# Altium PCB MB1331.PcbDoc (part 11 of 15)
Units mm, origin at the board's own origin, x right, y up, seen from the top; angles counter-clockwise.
Board outline 169.25 x 173.25 mm, 6 copper layers (Top Layer, Signal Layer 1, Signal Layer 2, Signal Layer 3, Signal Layer 4, Bottom Layer), stack 1.556 mm thick; 871 components, 699 nets, 3244 pads, 2370 vias.
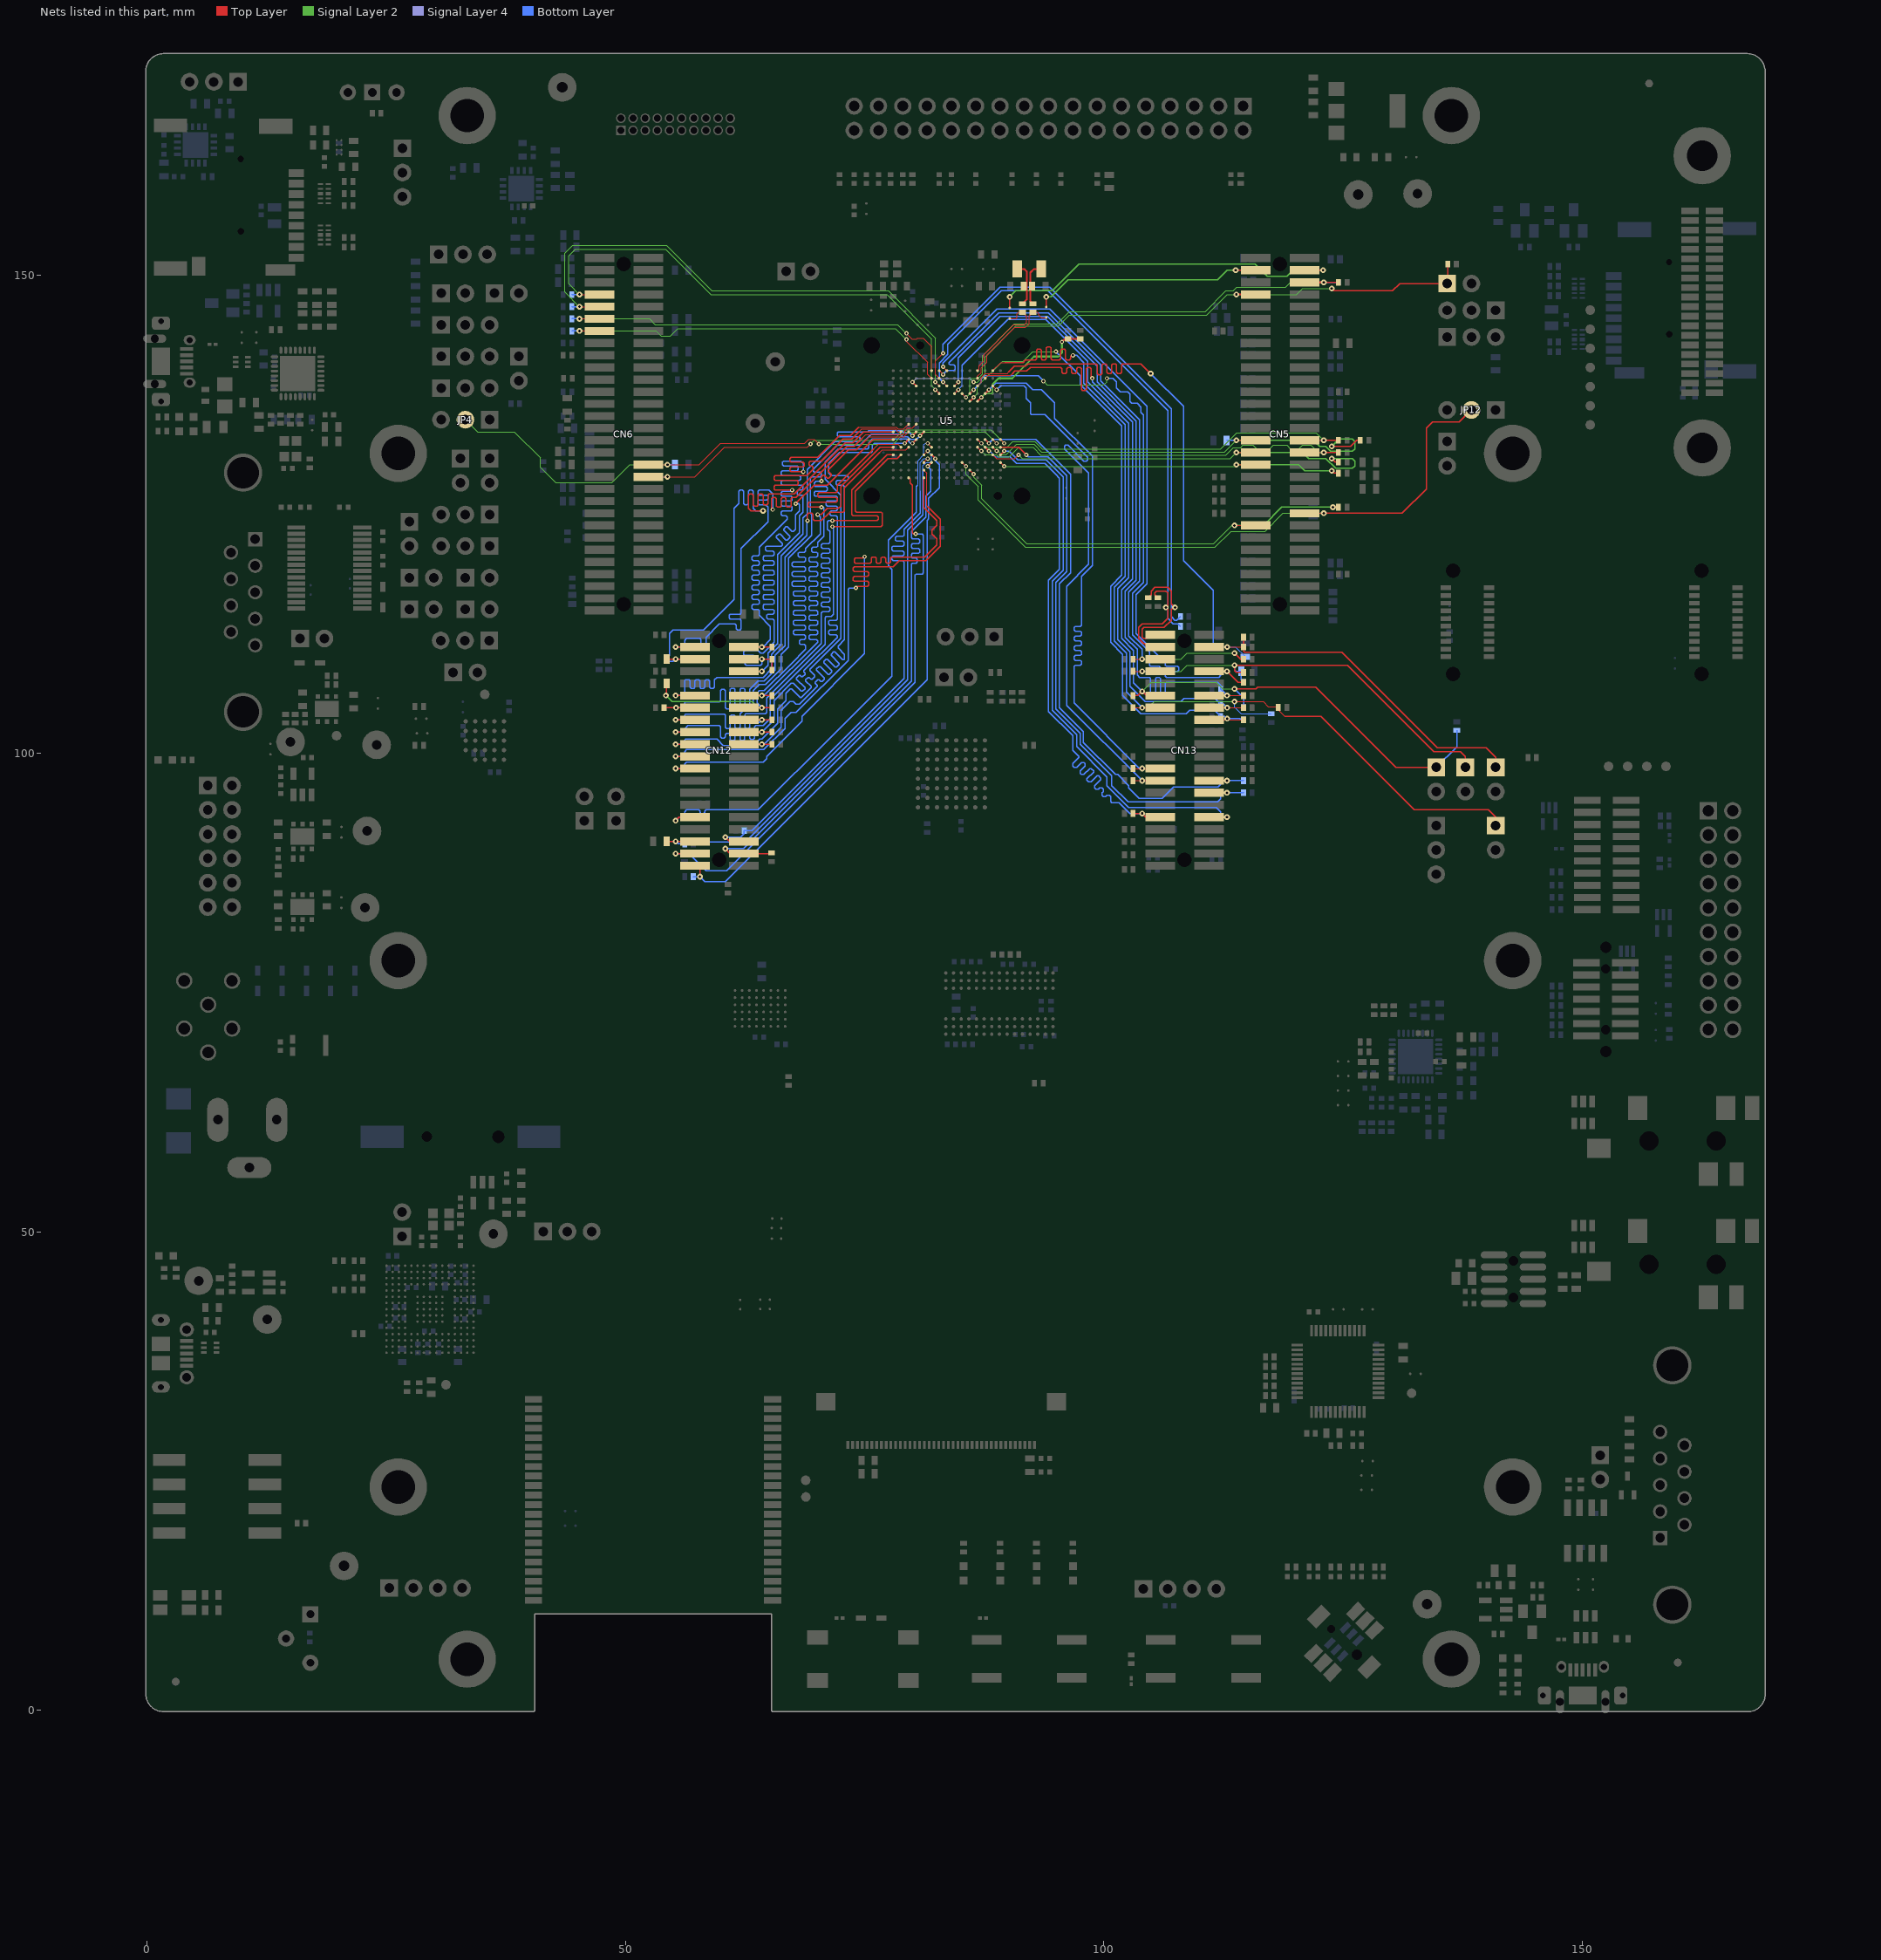
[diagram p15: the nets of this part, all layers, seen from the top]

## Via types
v1: diameter 0.6, hole 0.254, Top Layer to Bottom Layer, tented both sides, 1747 vias
v2: diameter 0.45, hole 0.2, Top Layer to Bottom Layer, tented both sides, 272 vias
v3: diameter 0.406, hole 0.203, Top Layer to Bottom Layer, tented both sides, 160 vias
v4: diameter 0.6, hole 0.25, Top Layer to Bottom Layer, tented both sides, 82 vias
v5: diameter 0.45, hole 0.25, Top Layer to Bottom Layer, tented both sides, 45 vias
v6: diameter 0.5, hole 0.25, Top Layer to Bottom Layer, tented both sides, 23 vias
v7: diameter 1.016, hole 0.508, Top Layer to Bottom Layer, tented both sides, 17 vias
v8: diameter 0.508, hole 0.254, Top Layer to Bottom Layer, tented both sides, 9 vias
v9: diameter 0.61, hole 0.305, Top Layer to Bottom Layer, tented both sides, 7 vias
v10: diameter 0.5, hole 0.254, Top Layer to Bottom Layer, tented both sides, 6 vias
v11: diameter 0.4, hole 0.2, Top Layer to Bottom Layer, tented both sides, 1 vias
v12: diameter 0.483, hole 0.254, Top Layer to Bottom Layer, tented both sides, 1 vias

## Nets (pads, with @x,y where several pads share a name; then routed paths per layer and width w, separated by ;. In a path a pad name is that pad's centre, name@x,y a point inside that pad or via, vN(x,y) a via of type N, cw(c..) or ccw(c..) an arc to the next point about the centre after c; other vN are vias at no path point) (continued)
PC8: CN5.44 JP12.2 U5.F13 | length 69.9
  Top Layer w0.1: U5.F13@85.2,130.4 v2(85.6,130) ; CN5.44@120.972,125.095 v1(122.994,125.095)
  Top Layer w0.127: v1(122.994,125.095) 131.191,125.095 133.731,127.635 133.731,133.985 134.366,134.62 137.16,134.62 JP12.2@138.43,135.89
  Signal Layer 2 w0.1: v2(85.6,130) 85.6,129.157 86.868,127.889 86.868,126.492 91.821,121.539 111.633,121.539 113.294,123.2 116.85,123.2 118.745,125.095 v1(122.994,125.095)
PC9: CN5.45 R62.2 U5.E14 | length 46.5
  Top Layer w0.1: U5.E14@86,129.6 v2(86.4,129.2) ; v1(113.665,123.825) CN5.45@115.872,123.825
  Top Layer w0.127: v1(123.952,125.73) R62.2@124.518,125.73
  Signal Layer 2 w0.1: v2(86.4,129.2) 86.4,128.865 87.249,128.016 87.249,126.619 91.948,121.92 111.506,121.92 113.411,123.825 v1(113.665,123.825)
  Signal Layer 2 w0.127: v1(113.665,123.825) 116.713,123.825 118.618,125.73 v1(123.952,125.73)
PC10: CN5.35 R56.2 U5.A13 | length 37.9
  Top Layer w0.1: U5.A13@89.2,130.4 v2(89.6,130) ; v1(113.85,130.175) CN5.35@115.872,130.175
  Top Layer w0.127: v1(123.825,129.54) 124.079,129.286 R56.2@124.518,129.286
  Signal Layer 2 w0.1: v2(89.6,130) 113.675,130 v1(113.85,130.175)
  Signal Layer 2 w0.127: v1(113.85,130.175) 120.396,130.175 121.031,129.54 v1(123.825,129.54)
PC11: CN5.34 R51.2 U5.D11 | length 42.4
  Top Layer w0.1: U5.D11@86.8,132 v2(87.2,131.6) ; CN5.34@120.972,131.445 v1(122.994,131.445)
  Top Layer w0.127: v1(122.994,131.445) R51.2@124.518,131.445
  Signal Layer 2 w0.1: v2(87.2,131.6) 87.6,131.2 88.8,131.2 89,131 90.1,131 91.1,132 92.6,132 93.409,131.191 112.776,131.191 113.538,131.953 114.3,131.953 114.554,132.207 115.57,132.207 116.078,131.699 117.221,131.699 117.729,132.207 119.126,132.207 119.507,131.826 120.396,131.826 120.777,132.207 121.666,132.207 122.428,131.445 v1(122.994,131.445)
PC12: CN5.33 R54.2 U5.B12 | length 45.3
  Top Layer w0.1: U5.B12@88.4,131.2 88.8,130.8 90.7,130.8 v2(91.1,131.2) ; v1(113.85,131.445) CN5.33@115.872,131.445
  Top Layer w0.127: v1(123.825,130.81) 124.206,130.429 R54.2@124.518,130.429
  Signal Layer 2 w0.1: v2(91.1,131.2) 91.49,130.81 113.215,130.81 v1(113.85,131.445)
  Signal Layer 2 w0.127: v1(113.85,131.445) 120.777,131.445 121.412,130.81 123.21,130.81 124.226,129.794 125.984,129.794 126.238,130.048 126.238,130.556 125.984,130.81 v1(123.825,130.81)
PC13: C97.1 CN5.6 R16.2 U5.F4 | length 49.9
  Top Layer w0.1: U5.F4@85.2,137.6 v2(85.6,137.2)
  Top Layer w0.127: v1(122.994,149.225) R16.2@124.518,149.225
  Top Layer w0.2: CN5.6@120.972,149.225 v1(122.994,149.225)
  Signal Layer 2 w0.1: v2(85.6,137.2) 86,137.6 86,139 86.2,139.2 86.876,139.2 87.33,139.654 87.33,141.559 90.678,144.907 95.123,144.907 96.393,146.177 110.617,146.177 112.776,148.336 113.555,148.336 113.919,148.7 119,148.7 119.525,149.225 v1(122.994,149.225)
  Bottom Layer w0.127: v1(122.994,149.225) C97.1@124.518,149.225
PC14: R23.2 SB8.2 U5.D1 | length 10.9
  Top Layer w0.1: U5.D1@86.8,140 86.973,140.173 86.973,140.507 87.477,141.011 87.477,141.677 90.58,144.78 91.694,144.78 91.948,145.034 91.948,145.652 R23.2@91.5,146.1 91.109,146.1 90.932,145.923 90.932,145.542 90.84,145.45 SB8.2@90.17,145.45
PC14-OSC32_IN: C25.2 R23.1 X2.2 | length 4.7
  Top Layer w0.2: X2.2@90.952,150.622 91.694,150.622 91.948,150.368 91.948,147.448 R23.1@91.5,147
PC14_E: CN5.4 SB8.1 | length 38.1
  Top Layer w0.127: SB8.1@90.17,146.55 v1(90.17,147.701) ; CN5.4@120.972,150.495 v1(122.936,150.495)
  Signal Layer 2 w0.127: v1(90.17,147.701) 90.805,148.336 94.615,148.336 97.409,151.13 115.824,151.13 117.094,149.86 119.126,149.86 119.761,150.495 v1(122.936,150.495)
PC15: R24.2 SB9.1 U5.D2 | length 11.6
  Top Layer w0.1: U5.D2@86.8,139.2 86.8,139.4 87.2,139.8 87.2,140.3 87.8,140.9 87.8,141.614 90.712,144.526 91.821,144.526 92.202,144.907 92.202,145.702 R24.2@92.6,146.1 93.041,146.1 93.218,145.923 93.218,145.796 93.464,145.55 SB9.1@93.98,145.55
PC15-OSC32_OUT: C26.2 R24.1 X2.1 | length 4.6
  Top Layer w0.2: R24.1@92.6,147 92.329,147.271 92.329,150.241 92.71,150.622 X2.1@93.452,150.622
PC15_E: CN5.3 SB9.2 | length 24.1
  Top Layer w0.127: SB9.2@93.98,146.65 v1(93.98,147.701) ; v1(113.792,150.495) CN5.3@115.872,150.495
  Signal Layer 2 w0.127: v1(93.98,147.701) 94.488,147.701 96.266,149.479 111.887,149.479 112.903,150.495 v1(113.792,150.495)
PD0: CN13.31 R119.1 U5.C11 | length 60.4
  Top Layer w0.127: U5.C11@87.6,132 v2(88,131.6) ; R119.1@103.066,93.726 v1(104.013,93.726) 104.394,93.345 CN13.31@105.892,93.345
  Bottom Layer w0.102: v2(88,131.6) 88.11,131.6 88.71,131 88.897,131
  Bottom Layer w0.127: 88.897,131 90.2,131 90.898,130.302 93.853,130.302 94.967,129.188 95.377,128.778 95.377,119.253 94.234,118.11 94.234,104.394 96.774,101.854 96.774,100.33 97.409,99.695 97.409,99.568 96.774,98.933 96.774,98.679 96.901,98.552 97.155,98.552 97.663,99.06 97.917,99.06 98.044,98.933 98.044,98.679 97.536,98.171 97.536,97.917 97.663,97.79 97.917,97.79 98.552,98.425 98.679,98.425 98.933,98.171 98.933,98.044 98.237,97.348 98.237,97.216 98.425,97.028 98.679,97.028 99.314,97.663 99.441,97.663 99.695,97.409 99.695,97.282 99.06,96.647 99.06,96.393 99.187,96.266 99.441,96.266 99.568,96.393 99.822,96.393 99.949,96.266 99.949,96.012 99.822,95.885 99.822,95.631 99.949,95.504 100.203,95.504 100.33,95.631 100.584,95.631 100.711,95.504 100.711,94.996 100.838,94.869 101.6,94.869 102.743,93.726 v1(104.013,93.726)
PD1: CN13.32 R373.1 U5.A12 | length 59.1
  Top Layer w0.127: U5.A12@89.2,131.2 v2(89.6,131.6) ; CN13.32@110.992,93.345 v1(112.881,93.345)
  Bottom Layer w0.127: v2(89.6,131.6) 90.1,131.6 91.017,130.683 93.98,130.683 95.758,128.905 95.758,119.126 94.615,117.983 94.615,104.521 97.155,101.981 97.155,100.711 100.33,97.536 100.33,96.647 102.616,94.361 111.76,94.361 112.21,93.911 R373.1@112.21,93.345 v1(112.881,93.345)
PD2: CN5.31 R49.1 R278.2 U5.B11 | length 49.9
  Top Layer w0.1: U5.B11@88.4,132 v2(88.8,131.6) ; v1(113.85,132.715) CN5.31@115.872,132.715
  Top Layer w0.127: v1(123.825,132.08) 125.788,132.08 126.423,132.715 R49.1@126.804,132.715
  Signal Layer 2 w0.1: v2(88.8,131.6) 88.975,131.6 89.375,131.2 89.8,131.2 90.9,132.3 92.7,132.3 93.5,131.5 112.635,131.5 v1(113.85,132.715)
  Signal Layer 2 w0.127: v1(113.85,132.715) 121.92,132.715 122.555,132.08 123.19,132.08 123.698,131.572 125.984,131.572 126.238,131.826 126.238,132.588 125.984,132.842 124.587,132.842 v1(123.825,132.08)
  Bottom Layer w0.127: R278.2@112.847,132.715 v1(113.85,132.715)
PD3: CN5.32 R48.1 U5.D10 | length 41.7
  Top Layer w0.1: U5.D10@86.8,132.8 v2(87.2,132.4) ; CN5.32@120.972,132.715 v1(122.994,132.715)
  Top Layer w0.127: v1(122.994,132.715) R48.1@124.518,132.715
  Signal Layer 2 w0.1: v2(87.2,132.4) 87.6,132 89.9,132 90.5,132.6 92.8,132.6 93.6,131.8 112.2,131.8 113.9,133.5 122.209,133.5 v1(122.994,132.715)
PD4: CN13.28 R367.2 R368.1 U5.A11 | length 60.6
  Top Layer w0.102: CN13.28@110.992,95.885 v1(112.881,95.885)
  Top Layer w0.127: U5.A11@89.2,132 91.1,132 v2(91.9,131.2)
  Bottom Layer w0.127: v2(91.9,131.2) 92.1,131 94.171,131 96.139,129.032 96.139,118.999 94.996,117.856 94.996,104.648 97.536,102.108 97.536,100.965 100.838,97.663 100.838,96.647 102.552,94.932 111.887,94.932 112.21,95.255 R368.1@112.21,95.885 v1(112.881,95.885) R367.2@114.612,95.885
PD5: CN13.26 R363.2 R364.1 U5.C10 | length 62.5
  Top Layer w0.102: CN13.26@110.992,97.155 v1(112.881,97.155)
  Top Layer w0.127: U5.C10@87.6,132.8 v2(88,132.4)
  Bottom Layer w0.127: v2(88,132.4) 88.4,132.8 92.879,132.8 96.52,129.159 96.52,118.872 95.377,117.729 95.377,104.775 97.853,102.298 97.853,101.155 101.219,97.79 101.473,97.79 102.616,96.647 102.616,96.393 103.695,95.313 106.108,95.313 107.295,96.5 111.931,96.5 112.21,96.779 R364.1@112.21,97.155 v1(112.881,97.155) R363.2@114.612,97.155
PD6: CN6.36 JP4.2 R284.2 U5.B10 | length 65.3
  Top Layer w0.1: CN6.36@52.393,130.175 v1(54.4,130.175) 57.719,130.175 59.944,132.4 68.745,132.4 69.145,132.8 69.765,132.8 v2(70.231,132.334) ; U5.B10@88.4,132.8 v2(88.8,132.4)
  Signal Layer 2 w0.1: JP4.2@33.275,134.875 34.55,133.6 38.4,133.6 41.1,130.9 41.1,129.9 42.7,128.3 48.6,128.3 50.475,130.175 v1(54.4,130.175) ; v2(70.231,132.334) 77.978,132.334 79.244,133.6 87.6,133.6 88.4,132.8 v2(88.8,132.4)
  Bottom Layer w0.127: v1(54.4,130.175) R284.2@55.18,130.175
PD7: CN6.38 R289.1 U5.A10 | length 41.2
  Top Layer w0.1: CN6.38@52.393,128.905 v1(54.4,128.905) 57.277,128.905 60.372,132 69.008,132 v2(69.342,132.334) ; U5.A10@89.2,132.8 v2(89.6,132.4)
  Signal Layer 2 w0.1: v2(69.342,132.334) 69.723,132.715 77.978,132.715 79.063,133.8 88.2,133.8 v2(89.6,132.4)
  Bottom Layer w0.1: R289.1@53.536,128.905 v1(54.4,128.905)
PD8: CN12.35 R123.2 R384.1 U5.L12 | length 60.9
  Top Layer w0.1: U5.L12@81.2,131.2 v2(81.6,131.6)
  Top Layer w0.127: R123.2@54.294,90.805 v1(55.251,90.805) CN12.35@57.273,90.805
  Bottom Layer w0.1: 81.1,129.794 81.1,130.059 81.441,130.4 81.8,130.4 82,130.6 82,131.2 v2(81.6,131.6)
  Bottom Layer w0.127: v1(55.251,90.805) 55.505,90.551 R384.1@56.192,90.551 56.192,90.93 56.385,91.123 58.229,91.123 58.61,90.742 62.547,90.742 79.502,107.696 79.502,123.317 81.1,124.915 81.1,129.794
PD9: CN12.37 R385.1 U5.N15 | length 59.3
  Top Layer w0.127: v1(55.251,89.535) CN12.37@57.273,89.535 ; U5.N15@79.6,128.8 79.756,128.644 79.756,128.27 80.01,128.016 80.01,123.063 80.137,122.936 v2(80.327,122.936)
  Bottom Layer w0.127: v1(55.251,89.535) 56.188,89.535 R385.1@56.188,89.604 56.573,89.604 58.42,87.757 60.579,87.757 80.264,107.442 80.264,118.618 80.391,118.745 81.026,118.745 81.153,118.872 81.153,122.809 81.026,122.936 v2(80.327,122.936)
PD10: CN12.36 R381.1 U5.L13 | length 58.6
  Top Layer w0.1: U5.L13@81.2,130.4 v2(81.6,130.8)
  Top Layer w0.127: v1(60.452,91.249) 60.896,90.805 CN12.36@62.373,90.805
  Bottom Layer w0.1: 80.8,127.418 80.8,130.4 81.2,130.8 v2(81.6,130.8)
  Bottom Layer w0.127: v1(60.452,91.249) 62.039,91.249 62.426,91.636 R381.1@62.426,91.948 63.246,91.948 79.121,107.823 79.121,120.015 78.994,120.142 77.978,120.142 77.851,120.269 77.851,120.523 77.978,120.65 78.994,120.65 79.121,120.777 79.121,121.031 78.994,121.158 77.978,121.158 77.851,121.285 77.851,121.539 77.978,121.666 78.994,121.666 79.121,121.793 79.121,122.047 78.994,122.174 78.359,122.174 78.232,122.301 78.232,122.555 78.359,122.682 78.994,122.682 79.121,122.809 79.121,123.444 80.8,125.123 80.8,127.418
PD11: CN12.21 R359.1 U5.L14 | length 59.9
  Top Layer w0.1: U5.L14@81.2,129.6 81.5,129.3 81.5,125.891 81.603,125.788
  Top Layer w0.127: v1(55.251,99.695) CN12.21@57.273,99.695 ; v2(74.104,117.284) 74.104,117.348 74.231,117.475 75.311,117.475 75.438,117.602 75.438,117.856 75.311,117.983 73.914,117.983 73.787,118.11 73.787,118.364 73.914,118.491 75.311,118.491 75.438,118.618 75.438,118.872 75.311,118.999 73.914,118.999 73.787,119.126 73.787,119.38 73.914,119.507 77.978,119.507 78.613,120.142 81.407,120.142 82.931,121.666 82.931,124.46 81.603,125.788
  Bottom Layer w0.127: v1(55.251,99.695) R359.1@56.188,99.695 56.188,100.2 56.388,100.4 64.459,100.4 66.675,102.616 66.675,103.632 67.31,104.267 67.818,104.267 73.279,109.728 73.279,117.157 73.406,117.284 v2(74.104,117.284)
PD12: CN12.23 R362.1 U5.L15 | length 58.7
  Top Layer w0.127: v1(55.251,98.425) CN12.23@57.273,98.425 ; v2(74.993,120.555) 74.835,120.396 74.041,120.396 73.914,120.269 73.914,120.015 74.041,119.888 75.565,119.888 75.692,120.015 75.692,120.396 75.819,120.523 76.105,120.523 76.2,120.428 76.2,120.015 76.327,119.888 76.581,119.888 76.708,120.015 76.708,120.396 76.835,120.523 77.057,120.523 77.216,120.364 77.216,120.015 77.343,119.888 77.597,119.888 77.724,120.015 77.724,120.428 77.819,120.523 81.28,120.523 82.55,121.793 82.55,122.428 82.042,122.936 82.042,123.317 82.55,123.825 82.55,124.333 81.2,125.683 U5.L15@81.2,128.8
  Bottom Layer w0.127: v1(55.251,98.425) R362.1@56.188,98.425 56.188,98.9 56.388,99.1 64.429,99.1 64.77,99.441 64.77,99.695 68.453,103.378 68.453,103.886 74.993,110.426 v2(74.993,120.555)
PD13: CN12.31 R375.1 U5.K11 | length 58.8
  Top Layer w0.1: v2(81.6,132.4) U5.K11@82,132
  Top Layer w0.127: v1(55.245,92.964) 55.626,93.345 CN12.31@57.273,93.345
  Bottom Layer w0.1: 80.525,128.023 80.6,128.098 80.6,130.6 81.2,131.2 81.2,132.254 81.346,132.4 v2(81.6,132.4)
  Bottom Layer w0.127: v1(55.245,92.964) 55.626,93.345 R375.1@56.188,93.345 56.188,93.907 56.388,94.107 57.658,94.107 57.785,93.98 57.785,93.853 57.912,93.726 58.166,93.726 58.293,93.853 58.293,93.98 58.42,94.107 63.881,94.107 71.755,101.981 77.851,108.077 77.851,119.253 77.47,119.634 77.47,122.301 80.391,125.222 80.391,127.889 80.525,128.023
PD14: CN12.39 R391.1 U5.K12 | length 59.4
  Top Layer w0.127: CN12.39@57.273,88.265 57.785,88.265 v1(57.785,87.122) ; U5.K12@82,131.2 v2(82.4,130.8)
  Bottom Layer w0.127: R391.1@57.092,87.122 v1(57.785,87.122) 58.307,86.6 60.438,86.6 81.534,107.696 81.534,124.334 81.7,124.5 81.7,126.658 82.804,127.762 82.804,130.175 82.4,130.579 v2(82.4,130.8)
PD15: CN12.38 R127.1 U5.K13 | length 59.7
  Top Layer w0.127: v1(60.452,90.043) 60.96,89.535 CN12.38@62.373,89.535 65.278,89.535 R127.1@65.278,89.604 ; v2(81.6,130) U5.K13@82,130.4
  Bottom Layer w0.127: v1(60.452,90.043) 62.357,90.043 79.883,107.569 79.883,119.761 80.01,119.888 80.391,119.888 80.518,120.015 80.518,120.269 80.391,120.396 80.01,120.396 79.883,120.523 79.883,120.777 80.01,120.904 80.645,120.904 80.772,121.031 80.772,121.285 80.645,121.412 80.01,121.412 79.883,121.539 79.883,121.793 80.01,121.92 80.645,121.92 80.772,122.047 80.772,122.301 80.645,122.428 80.01,122.428 79.883,122.555 79.883,123.19 81.4,124.707 81.4,126.873 81.915,127.388 81.915,129.685 v2(81.6,130)
PDR_ON: R30.1 R31.2 U5.D5 | length 14.6
  Top Layer w0.2: U5.D5@86.8,136.8 v2(87.2,137.2) ; v2(95.631,143.002) 95.943,143.314 R30.1@96.266,143.314 R31.2@97.536,143.314
  Signal Layer 2 w0.127: v2(87.2,137.2) 87.6,137.6 88.3,137.6 88.4,137.7 88.4,138.6
  Signal Layer 2 w0.2: 88.4,138.6 88.992,139.192 90.424,139.192 92.71,141.478 95.25,141.478 95.631,141.859 v2(95.631,143.002)
PE0: CN13.25 R117.1 U5.B3 | length 61.1
  Top Layer w0.1: U5.B3@88.4,138.4 v2(88.8,138)
  Top Layer w0.102: R117.1@103.066,97.155 v1(104.013,97.155) CN13.25@105.892,97.155
  Bottom Layer w0.127: v2(88.8,138) 89.23,138.43 91.67,138.43 91.9,138.2 91.9,137.097 92.337,136.66 92.337,135.509 92.449,135.397 93.838,135.397 96.71,132.524 98.298,130.937 98.298,130.683 98.171,130.556 97.917,130.556 96.266,132.207 96.012,132.207 95.885,132.08 95.885,131.826 98.425,129.286 98.425,119.761 96.139,117.475 96.139,105.029 v1(104.013,97.155)
PE1: CN13.23 R114.1 U5.C4 | length 60.3
  Top Layer w0.102: R114.1@103.066,98.425 v1(104.013,98.425) CN13.23@105.892,98.425
  Top Layer w0.127: U5.C4@87.6,137.6 v2(88,138)
  Bottom Layer w0.127: v2(88,138) 88.684,138.684 91.9,138.684 92.584,138 93.5,138 94.869,136.631 94.869,135.001 98.806,131.064 98.806,119.634 97.663,118.491 97.663,113.411 97.536,113.284 97.028,113.284 96.901,113.157 96.901,112.903 97.028,112.776 97.536,112.776 97.663,112.649 97.663,112.395 97.536,112.268 97.028,112.268 96.901,112.141 96.901,111.887 97.028,111.76 97.536,111.76 97.663,111.633 97.663,111.379 97.536,111.252 97.028,111.252 96.901,111.125 96.901,110.871 97.028,110.744 97.536,110.744 97.663,110.617 97.663,110.363 97.536,110.236 97.028,110.236 96.901,110.109 96.901,109.855 97.028,109.728 97.536,109.728 97.663,109.601 97.663,109.347 97.536,109.22 97.028,109.22 96.901,109.093 96.901,105.283 103.759,98.425 v1(104.013,98.425)
PE2: CN13.16 R101.2 R342.1 R343.2 U5.E5 | length 68.6
  Top Layer w0.102: CN13.16@110.992,103.505 112.776,103.505 v1(112.903,103.632) 113.03,103.505 R101.2@114.362,103.505
  Top Layer w0.127: U5.E5@86,136.8 v2(86.4,137.2)
  Signal Layer 2 w0.1: v2(86.4,137.2) 86.8,137.6 86.8,138.362 89.408,140.97 91.567,140.97 92.583,141.986 v2(94.996,141.986)
  Bottom Layer w0.127: v2(94.996,141.986) 97.536,139.446 97.536,138.557 101.854,134.239 101.854,118.618 100.711,117.475 100.711,111.633 101.981,110.363 101.981,106.045 103.886,104.14 108.6,104.14 108.96,104.5 111.596,104.5 R342.1@112.21,103.886 112.649,103.886 v1(112.903,103.632) 114.235,103.632 R343.2@114.362,103.505
PE3: CN13.13 JP34.1 R93.2 R97.1 R337.2 U5.B1 | length 107.4
  Top Layer w0.1: U5.B1@88.4,140 89.243,140.843 89.662,140.843 ; v1(113.665,105.41) 116.67,105.41 117.205,104.875 118.175,104.875 R93.2@118.25,104.8 118.25,104.536 118.9,103.886
  Top Layer w0.102: R97.1@103.066,104.775 v1(104.013,104.775) CN13.13@105.892,104.775
  Top Layer w0.127: 89.662,140.843 91.567,140.843 91.821,141.097 92.837,141.097 92.964,141.224 92.964,142.113 93.091,142.24 93.345,142.24 93.472,142.113 93.472,141.224 93.599,141.097 93.853,141.097 93.98,141.224 93.98,142.367 94.107,142.494 94.361,142.494 94.488,142.367 94.488,141.224 94.615,141.097 95.377,141.097 95.504,141.224 95.504,142.113 95.631,142.24 95.885,142.24 96.012,142.113 96.012,141.224 96.139,141.097 96.393,141.097 96.52,141.224 96.52,141.478 96.647,141.605 v2(96.774,141.605) ; 118.9,103.886 122.682,103.886 132.461,94.107 140.208,94.107 140.97,93.345 JP34.1@140.97,92.456
  Signal Layer 2 w0.1: v1(104.013,104.775) 104.648,104.775 105.283,105.41 v1(113.665,105.41)
  Bottom Layer w0.1: v1(113.665,105.41) 113.665,104.835 114.35,104.15 R337.2@117.5,104.15
  Bottom Layer w0.127: v2(96.774,141.605) 97.155,141.605 97.917,140.843 97.917,138.684 102.235,134.366 102.235,118.491 101.092,117.348 101.092,111.76 102.362,110.49 102.362,106.426 v1(104.013,104.775)
PE4: CN13.11 JP26.1 R88.1 R116.2 R340.2 U5.C2 | length 100.4
  Top Layer w0.1: U5.C2@87.6,139.2 87.9,139.5 90.259,139.5 90.424,139.665
  Top Layer w0.127: 90.424,139.665 90.713,139.954 91.948,139.954 92.329,140.335 95.504,140.335 95.631,140.208 95.631,139.827 95.758,139.7 96.012,139.7 96.139,139.827 96.139,140.208 96.266,140.335 96.52,140.335 96.647,140.208 96.647,139.827 96.774,139.7 97.028,139.7 97.155,139.827 97.155,140.208 97.282,140.335 97.536,140.335 97.663,140.208 97.663,138.049 97.79,137.922 98.044,137.922 98.171,138.049 98.171,140.208 98.298,140.335 98.552,140.335 98.679,140.208 98.679,139.827 98.68,139.826 98.68,139.318 98.798,139.2 v2(98.8,139.2) ; R88.1@103.066,106.045 103.568,106.045 v1(104.013,106.489) 104.457,106.045 CN13.11@105.892,106.045 ; v1(113.665,106.743) 115.887,106.743 116.078,106.934 122.174,106.934 130.556,98.552 JP26.1@134.747,98.552
  Signal Layer 2 w0.1: v1(104.013,106.489) 104.965,107.442 111.76,107.442 112.458,106.743 v1(113.665,106.743)
  Bottom Layer w0.127: v2(98.8,139.2) 98.8,138.817 102.997,134.62 102.997,118.237 101.854,117.094 101.854,112.014 103.124,110.744 103.124,107.378 v1(104.013,106.489) ; v1(113.665,106.743) 114.363,106.045 114.612,106.045 R340.2@114.612,104.775 ; JP26.1@134.747,98.552 136.9,100.705 R116.2@136.9,102.4
PE5: CN13.4 JP28.1 R69.2 R71.2 R323.2 R324.1 U5.D3 | length 97.4
  Top Layer w0.1: U5.D3@86.8,138.4 87.2,138.8 87.2,139.3 87.6,139.7 89.916,139.7 90.07,139.854
  Top Layer w0.102: CN13.4@110.992,111.125 v1(112.903,111.125) R71.2@114.612,111.125
  Top Layer w0.127: 90.07,139.854 90.678,140.462 91.821,140.462 92.075,140.716 99.187,140.716 99.314,140.589 99.314,139.7 99.441,139.573 99.695,139.573 99.822,139.7 99.822,140.589 99.949,140.716 100.203,140.716 100.33,140.589 100.33,139.827 100.457,139.7 100.711,139.7 100.838,139.827 100.838,140.589 100.965,140.716 101.219,140.716 101.346,140.589 101.346,139.827 101.473,139.7 101.727,139.7 101.854,139.827 101.854,140.589 101.981,140.716 103.886,140.716 v1(104.902,139.7) ; R69.2@114.612,112.141 R71.2@114.612,111.125 114.612,110.686 114.744,110.553 124.904,110.553 134.874,100.584 139.954,100.584 140.97,99.568 JP28.1@140.97,98.552
  Bottom Layer w0.1: v1(112.903,111.125) 113.775,111.125 R323.2@114.8,110.1
  Bottom Layer w0.127: v1(104.902,139.7) 108.331,136.271 108.331,120.142 111.432,117.041 R324.1@111.432,111.125 v1(112.903,111.125)
PE6: CN13.7 JP27.1 R78.1 R80.2 R330.2 R334.2 U5.E4 | length 100.3
  Top Layer w0.1: U5.E4@86,137.6 v2(86.4,138)
  Top Layer w0.102: R78.1@103.066,108.585 v1(104.013,108.585) CN13.7@105.892,108.585
  Top Layer w0.127: R80.2@114.612,108.458 113.855,108.458 113.665,108.648 v1(113.665,109.22) 125.476,109.22 134.493,100.203 137.287,100.203 137.795,99.695 JP27.1@137.795,98.552
  Signal Layer 2 w0.102: v5(93.7,138.9) 94.1,138.5 99.9,138.5 100.33,138.8 v2(100.33,139.192) ; v1(104.013,108.585) 108.077,108.585 108.712,109.22 v1(113.665,109.22)
  Bottom Layer w0.127: v2(86.4,138) 87.2,138.8 87.2,139.143 87.503,139.446 93.154,139.446 v5(93.7,138.9) ; v2(100.33,139.192) 100.965,139.192 101.346,138.811 101.346,138.176 101.727,137.795 102.489,137.795 102.743,137.541 102.743,136.779 102.933,136.588 103.505,136.588 103.886,136.207 103.886,135.636 104.14,135.382 104.14,117.856 102.997,116.713 102.997,112.395 104.775,110.617 104.775,110.236 104.902,110.109 105.156,110.109 105.283,109.982 105.283,109.728 105.156,109.601 104.902,109.601 104.775,109.474 104.775,109.22 104.902,109.093 105.791,109.093 105.918,108.966 105.918,108.712 105.791,108.585 v1(104.013,108.585) ; v1(113.665,109.22) 113.665,108.712 113.792,108.585 R330.2@114.362,108.585 114.362,107.692 R334.2@114.612,107.442
PE7: CN12.11 R338.1 U5.M9 | length 59.6
  Top Layer w0.127: v1(55.251,106.045) CN12.11@57.273,106.045 ; v2(80,133.2) U5.M9@80.4,133.6
  Bottom Layer w0.127: v1(55.251,106.045) R338.1@56.188,106.045 56.188,106.426 56.188,107.623 56.261,107.696 56.642,107.696 56.769,107.569 56.769,106.934 56.896,106.807 57.15,106.807 57.277,106.934 57.277,107.569 57.404,107.696 57.658,107.696 57.785,107.569 57.785,106.934 57.912,106.807 58.166,106.807 58.293,106.934 58.293,107.569 58.42,107.696 58.674,107.696 58.801,107.569 58.801,106.934 58.928,106.807 59.182,106.807 59.309,106.934 59.309,107.696 59.563,107.95 64.389,107.95 65.278,108.839 65.278,110.363 65.659,110.744 66.294,111.379 66.294,120.65 68.58,122.936 68.58,124.587 69,125.007 69,129.686 71.902,132.588 74.422,132.588 74.549,132.715 74.549,132.969 74.422,133.096 72.263,133.096 72.136,133.223 72.136,133.477 72.263,133.604 75.331,133.604 75.438,133.711 78.887,133.711 79.121,133.477 79.723,133.477 v2(80,133.2)
PE8: CN12.14 R81.2 R96.1 U5.R11 | length 71.3
  Top Layer w0.127: v1(54.229,106.045) 54.294,106.11 R81.2@54.294,107.315 ; CN12.14@62.373,104.775 v1(64.262,104.775) R96.1@65.336,104.775 ; v2(70.104,124.968) 70.485,124.968 71.12,125.603 72.263,125.603 72.517,125.857 72.517,127.889 76.628,132 U5.R11@78,132
  Signal Layer 2 w0.127: v1(54.229,106.045) 54.864,105.41 63.246,105.41 63.881,104.775 v1(64.262,104.775)
  Bottom Layer w0.127: v1(64.262,104.775) 63.754,105.283 63.754,106.299 64.008,106.553 64.516,106.553 67.31,109.347 68.834,110.871 68.834,111.252 68.707,111.379 68.326,111.379 68.199,111.506 68.199,111.76 68.326,111.887 68.707,111.887 68.834,112.014 68.834,112.268 68.707,112.395 67.691,112.395 67.564,112.522 67.564,112.776 67.691,112.903 68.707,112.903 68.834,113.03 68.834,113.284 68.707,113.411 67.691,113.411 67.564,113.538 67.564,113.792 67.691,113.919 68.707,113.919 68.834,114.046 68.834,114.3 68.707,114.427 67.691,114.427 67.564,114.554 67.564,114.808 67.691,114.935 68.707,114.935 68.834,115.062 68.834,115.316 68.707,115.443 67.691,115.443 67.564,115.57 67.564,115.824 67.691,115.951 68.707,115.951 68.834,116.078 68.834,116.332 68.707,116.459 67.691,116.459 67.564,116.586 67.564,116.84 67.691,116.967 68.707,116.967 68.834,117.094 68.834,117.348 68.707,117.475 67.564,117.475 67.437,117.602 67.437,117.856 67.564,117.983 68.707,117.983 68.834,118.11 68.834,118.364 68.707,118.491 67.564,118.491 67.437,118.618 67.437,118.872 67.564,118.999 68.707,118.999 68.834,119.126 68.834,119.38 68.707,119.507 67.564,119.507 67.437,119.634 67.437,119.888 67.564,120.015 68.707,120.015 68.834,120.142 68.834,120.396 68.707,120.523 68.199,120.523 68.072,120.65 68.072,120.904 68.199,121.031 68.707,121.031 68.834,121.158 68.834,121.412 70.358,122.936 70.358,124.714 v2(70.104,124.968)
PE9: CN12.12 R87.1 U5.P11 | length 58.8
  Top Layer w0.1: 75.946,131.826 76.42,132.3 78.5,132.3 U5.P11@78.8,132
  Top Layer w0.127: CN12.12@62.373,106.045 v1(64.262,106.045) R87.1@65.336,106.045 ; v2(70.485,125.73) 69.215,125.73 69.088,125.857 69.088,126.111 69.215,126.238 72.009,126.238 72.136,126.365 72.136,126.619 72.009,126.746 70.231,126.746 70.104,126.873 70.104,127.127 70.231,127.254 72.009,127.254 72.136,127.381 72.136,128.016 75.946,131.826
  Bottom Layer w0.127: v1(64.262,106.045) 64.516,106.045 70.104,111.633 70.104,111.76 69.977,111.887 69.342,111.887 69.215,112.014 69.215,112.268 69.342,112.395 69.977,112.395 70.104,112.522 70.104,112.776 69.977,112.903 69.342,112.903 69.215,113.03 69.215,113.284 69.342,113.411 69.977,113.411 70.104,113.538 70.104,113.792 69.977,113.919 69.342,113.919 69.215,114.046 69.215,114.3 69.342,114.427 69.977,114.427 70.104,114.554 70.104,114.808 69.977,114.935 69.342,114.935 69.215,115.062 69.215,115.316 69.342,115.443 69.977,115.443 70.104,115.57 70.104,115.824 69.977,115.951 69.342,115.951 69.215,116.078 69.215,116.332 69.342,116.459 69.977,116.459 70.104,116.586 70.104,116.84 69.977,116.967 69.342,116.967 69.215,117.094 69.215,117.348 69.342,117.475 69.977,117.475 70.104,117.602 70.104,117.856 69.977,117.983 69.342,117.983 69.215,118.11 69.215,118.364 69.342,118.491 69.977,118.491 70.104,118.618 70.104,118.872 69.977,118.999 69.342,118.999 69.215,119.126 69.215,119.38 69.342,119.507 69.977,119.507 70.104,119.634 70.104,119.888 69.977,120.015 69.342,120.015 69.215,120.142 69.215,120.396 69.342,120.523 69.977,120.523 70.104,120.65 70.104,120.904 69.977,121.031 69.596,121.031 69.469,121.158 69.469,121.412 69.596,121.539 69.977,121.539 70.104,121.666 70.104,122.047 70.739,122.682 70.739,125.666 70.675,125.73 v2(70.485,125.73)
PE10: CN12.13 R95.2 R341.1 U5.N11 | length 60.7
  Top Layer w0.1: 76.564,131.428 76.836,131.7 79.3,131.7 U5.N11@79.6,132
  Top Layer w0.127: R95.2@54.044,104.775 v1(55.3,104.775) CN12.13@57.273,104.775 ; v2(69.024,124.333) 69.024,124.968 69.151,125.095 69.469,125.095 69.596,124.968 69.596,124.46 69.723,124.333 70.485,124.333 71.374,125.222 72.771,125.222 72.898,125.349 72.898,127.762 76.564,131.428
  Bottom Layer w0.127: v1(55.3,104.775) R341.1@56.188,104.775 56.188,105.327 56.261,105.4 59.817,105.4 59.944,105.527 59.944,106.553 60.071,106.68 60.325,106.68 60.452,106.553 60.452,104.775 60.579,104.648 60.833,104.648 60.96,104.775 60.96,106.68 61.087,106.807 61.341,106.807 61.468,106.68 61.468,104.775 61.595,104.648 61.849,104.648 61.976,104.775 61.976,106.68 62.103,106.807 62.357,106.807 62.484,106.68 62.484,105.156 62.611,105.029 62.865,105.029 62.992,105.156 62.992,106.68 63.881,107.569 64.516,107.569 65.659,108.712 65.659,110.236 65.976,110.553 66.675,111.252 66.675,120.523 68.961,122.809 68.961,124.269 v2(69.024,124.333)
PE11: CN12.16 R102.1 U5.R12 | length 59.6
  Top Layer w0.127: CN12.16@62.373,103.505 v1(64.262,103.505) R102.1@65.336,103.505 ; v2(71.628,124.333) 76.327,124.333 76.454,124.46 76.454,124.714 76.327,124.841 73.787,124.841 73.66,124.968 73.66,127.508 77.352,131.2 U5.R12@78,131.2
  Bottom Layer w0.127: v1(64.262,103.505) 64.008,103.251 63.119,103.251 62.992,103.124 62.992,102.743 62.865,102.616 62.611,102.616 62.484,102.743 62.484,104.076 62.547,104.14 64.643,104.14 64.77,104.267 64.77,105.791 70.485,111.506 70.485,114.681 70.612,114.808 71.247,114.808 71.374,114.935 71.374,115.189 71.247,115.316 70.612,115.316 70.485,115.443 70.485,115.697 70.612,115.824 71.247,115.824 71.374,115.951 71.374,116.205 71.247,116.332 70.612,116.332 70.485,116.459 70.485,116.713 70.612,116.84 71.247,116.84 71.374,116.967 71.374,117.221 71.247,117.348 70.612,117.348 70.485,117.475 70.485,117.729 70.612,117.856 71.247,117.856 71.374,117.983 71.374,118.237 71.247,118.364 70.612,118.364 70.485,118.491 70.485,118.745 70.612,118.872 71.247,118.872 71.374,118.999 71.374,119.253 71.247,119.38 70.612,119.38 70.485,119.507 70.485,119.761 70.612,119.888 71.247,119.888 71.374,120.015 71.374,120.269 71.247,120.396 70.612,120.396 70.485,120.523 70.485,120.777 70.612,120.904 71.247,120.904 71.374,121.031 71.374,121.285 71.247,121.412 70.612,121.412 70.485,121.539 70.485,121.793 70.612,121.92 71.247,121.92 71.374,122.047 71.374,123.19 71.12,123.444 71.12,124.206 71.247,124.333 v2(71.628,124.333)
PE12: CN12.15 R345.1 U5.L9 | length 59.5
  Top Layer w0.127: v1(55.251,103.505) CN12.15@57.273,103.505 ; v2(80.8,133.2) U5.L9@81.2,133.6
  Bottom Layer w0.127: v1(55.251,103.505) R345.1@56.188,103.505 56.188,104.027 56.261,104.1 60.365,104.1 60.452,104.013 60.452,102.743 60.579,102.616 60.833,102.616 60.96,102.743 60.96,103.886 61.087,104.013 61.341,104.013 61.468,103.886 61.468,102.743 61.595,102.616 61.849,102.616 61.976,102.743 61.976,104.14 62.484,104.648 63.246,104.648 63.373,104.775 63.373,106.553 64.008,107.188 64.643,107.188 66.294,108.839 66.294,110.363 67.056,111.125 67.056,120.396 69.469,122.809 69.469,124.968 69.342,125.095 69.342,128.778 69.469,128.905 70.358,128.905 70.485,129.032 70.485,129.286 70.358,129.413 69.747,129.413 69.659,129.501 69.659,129.731 72.136,132.207 74.549,132.207 75.692,133.35 78.74,133.35 78.994,133.096 79.504,133.096 79.8,132.8 80.4,132.8 v2(80.8,133.2)
PE13: CN12.19 R353.1 U5.M10 | length 59.7
  Top Layer w0.127: v1(55.251,100.965) CN12.19@57.273,100.965 ; v2(80,132.4) U5.M10@80.4,132.8
  Bottom Layer w0.127: v1(55.251,100.965) R353.1@56.188,100.965 56.188,101.427 56.261,101.5 59.563,101.5 60.225,100.838 63.373,100.838 64.035,101.5 64.289,101.5 65.913,103.124 65.913,104.648 66.802,105.537 66.802,106.299 67.246,106.743 67.373,106.743 68.262,105.855 68.389,105.855 69.405,106.87 69.405,106.998 68.834,107.569 68.834,107.696 69.088,107.95 69.215,107.95 69.405,107.759 69.532,107.759 69.786,108.013 69.786,108.14 69.278,108.648 69.278,108.775 72.517,112.014 72.517,127 70.866,128.651 70.866,130.429 72.263,131.826 75.311,131.826 75.438,131.953 75.438,132.461 75.819,132.842 79.358,132.842 79.8,132.4 v2(80,132.4)
PE14: CN12.20 R105.1 U5.N10 | length 59.1
  Top Layer w0.127: CN12.20@62.373,100.965 v1(64.262,100.965) R105.1@65.336,100.965 ; v2(79.2,132.4) U5.N10@79.6,132.8
  Bottom Layer w0.127: v1(64.262,100.965) 64.516,100.965 66.294,102.743 66.294,104.521 67.183,105.41 67.564,105.41 67.818,105.156 68.199,105.156 70.04,106.998 70.04,107.124 69.85,107.315 69.85,107.442 70.104,107.696 70.231,107.696 70.421,107.505 70.548,107.505 70.802,107.759 70.802,107.886 69.991,108.698 69.991,108.825 70.243,109.077 70.374,109.077 71.183,108.267 71.31,108.267 71.564,108.521 71.564,108.648 70.739,109.474 70.739,109.601 70.993,109.855 71.12,109.855 71.945,109.029 72.072,109.029 72.326,109.283 72.326,109.41 71.501,110.236 71.501,110.363 71.755,110.617 71.882,110.617 72.707,109.791 72.834,109.791 72.898,109.855 72.898,110.363 72.231,111.03 72.231,111.22 72.898,111.887 72.898,127.889 72.771,128.016 72.136,128.016 72.009,128.143 72.009,128.397 72.136,128.524 73.152,128.524 73.279,128.651 73.279,128.905 73.152,129.032 71.501,129.032 71.247,129.286 71.247,130.302 72.39,131.445 75.692,131.445 75.819,131.572 75.819,132.207 76.012,132.4 v2(79.2,132.4)
PE15: CN12.17 R348.1 U5.P12 | length 59.4
  Top Layer w0.127: v1(55.251,102.235) CN12.17@57.273,102.235 ; v2(71.628,123.698) 76.708,123.698 76.835,123.825 76.835,125.095 76.708,125.222 74.168,125.222 74.041,125.349 74.041,127.381 77.46,130.8 78.4,130.8 U5.P12@78.8,131.2
  Bottom Layer w0.127: v1(55.251,102.235) R348.1@56.188,102.235 56.188,102.573 56.515,102.9 59.817,102.9 59.944,102.773 59.944,101.727 60.071,101.6 60.325,101.6 60.452,101.727 60.452,101.981 60.579,102.108 60.833,102.108 60.96,101.981 60.96,101.473 61.087,101.346 61.341,101.346 61.468,101.473 61.468,101.981 61.595,102.108 61.849,102.108 61.976,101.981 61.976,101.473 62.103,101.346 62.342,101.346 62.469,101.473 62.469,101.981 62.596,102.108 62.865,102.108 62.992,101.981 62.992,101.6 63.119,101.473 63.373,101.473 63.5,101.6 63.5,102.773 63.627,102.9 64.419,102.9 65.151,103.632 65.151,105.664 70.866,111.379 70.866,114.173 70.993,114.3 71.501,114.3 71.755,114.554 71.755,123.571 v2(71.628,123.698)
PF0: CN13.14 R98.2 R339.1 U5.G4 | length 71.9
  Top Layer w0.1: U5.G4@84.4,137.6 v2(84.8,138)
  Top Layer w0.102: CN13.14@110.992,104.775 v1(112.903,104.775) R98.2@114.612,104.775
  Bottom Layer w0.1: v2(84.8,138) 85.2,138.4 85.2,139.131
  Bottom Layer w0.127: 85.2,139.131 85.2,140.572 89.916,145.288 89.957,145.329 93.939,145.329 98.298,140.97 98.298,138.811 102.616,134.493 102.616,118.364 101.473,117.221 101.473,111.887 102.743,110.617 102.743,106.997 104.33,105.41 108.077,105.41 108.394,105.727 111.639,105.727 R339.1@112.21,105.156 112.522,105.156 v1(112.903,104.775)
PF1: CN13.12 R89.2 R335.1 U5.G3 | length 75.9
  Top Layer w0.1: U5.G3@84.4,138.4 v2(84.8,138.8)
  Top Layer w0.102: CN13.12@110.992,106.045 v1(112.881,106.045) R89.2@114.612,106.045
  Bottom Layer w0.127: v2(84.8,138.8) 84.8,141.315 89.154,145.669 94.107,145.669 99.3,140.476 99.3,138.825 103.378,134.747 103.378,118.11 102.235,116.967 102.235,112.141 103.505,110.871 103.505,108.204 103.759,107.95 104.775,107.95 104.902,107.823 104.902,106.426 105.029,106.299 105.283,106.299 105.41,106.426 105.41,107.823 105.537,107.95 105.791,107.95 105.918,107.823 105.918,106.426 106.045,106.299 106.299,106.299 106.426,106.426 106.426,107.315 106.553,107.442 111.887,107.442 112.21,107.119 R335.1@112.21,106.68 112.246,106.68 v1(112.881,106.045)
PF2: CN13.8 R82.2 R331.1 U5.H1 | length 72.4
  Top Layer w0.1: v2(83.2,140.4) U5.H1@83.6,140
  Top Layer w0.102: CN13.8@110.992,108.585 v1(112.881,108.585)
  Top Layer w0.127: v1(112.881,108.585) 114.024,107.442 R82.2@114.612,107.442
  Bottom Layer w0.127: v2(83.2,140.4) 83.2,140.8 86.5,144.1 88.831,146.431 94.361,146.431 104.521,136.271 104.521,117.729 103.378,116.586 103.378,112.522 106.426,109.474 106.426,109.22 106.553,109.093 107.696,109.093 107.823,108.966 107.823,108.712 107.696,108.585 106.553,108.585 106.426,108.458 106.426,108.077 106.553,107.95 112.014,107.95 112.21,108.146 R331.1@112.21,108.585 v1(112.881,108.585)
PF3: CN13.5 R74.1 R75.2 U5.J1 | length 71
  Top Layer w0.1: U5.J1@82.8,140 v2(83.2,139.6)
  Top Layer w0.102: R74.1@103.066,109.855 v1(104.003,109.855) CN13.5@105.892,109.855
  Top Layer w0.127: v1(113.665,110.49) 114.3,109.855 R75.2@114.612,109.855
  Signal Layer 2 w0.1: v1(104.003,109.855) 108.077,109.855 108.712,110.49 v1(113.665,110.49)
  Bottom Layer w0.127: v2(83.2,139.6) 83.6,140 84.329,140 84.455,140.126 84.455,140.462 84.328,140.589 83.947,140.589 83.82,140.716 83.82,140.843 89.027,146.05 94.234,146.05 99.7,140.584 99.7,138.933 103.759,134.874 103.759,117.983 102.616,116.84 102.616,112.268 104.003,110.881 v1(104.003,109.855)
PF4: CN13.3 R66.1 R319.2 U5.H3 | length 71.3
  Top Layer w0.1: v2(83.2,138.8) U5.H3@83.6,138.4
  Top Layer w0.13: R66.1@105.664,116.274 105.346,116.591 105.346,116.776 105.537,116.967 106.489,116.967 106.68,116.776 106.68,115.443 v1(106.489,115.252) 106.68,115.062 106.68,114.109 106.108,113.538 104.013,113.538 103.632,113.157 103.632,112.014 104.14,111.506 104.267,111.506 104.648,111.125 CN13.3@105.892,111.125
  Bottom Layer w0.13: v2(83.2,138.8) 82.8,139.2 82.8,140.8 83.693,141.693 83.693,142.748 89.281,148.336 94.17,148.336 106.68,135.826 v1@106.68,115.252 ; v1(106.489,115.252) v1@106.68,115.252 ; R319.2@108.008,113.284 107.754,113.538 107.251,113.538 106.68,114.109 v1@106.68,115.252
PF5: CN13.1 R65.1 R318.2 U5.J2 | length 72.1
  Top Layer w0.1: U5.J2@82.8,139.2 82.4,139.6 82.4,141 v2(83.2,141.8)
  Top Layer w0.13: R65.1@104.648,116.274 104.965,116.591 104.965,116.967 105.346,117.348 106.68,117.348 107.061,116.967 107.061,115.633 v1(107.442,115.252) 107.251,115.252 107.061,115.062 107.061,113.919 106.299,113.157 104.203,113.157 104.013,112.966 104.013,112.141 104.14,112.014 104.521,112.014 104.902,112.395 CN13.1@105.892,112.395
  Bottom Layer w0.13: v2(83.2,141.8) 83.2,142.763 89.154,148.717 94.361,148.717 107.061,136.017 107.061,115.252 ; v1(107.442,115.252) 107.061,115.252 ; R318.2@108.008,114.3 107.627,113.919 107.442,113.919 107.061,114.3 107.061,115.252
PF6: CN6.9 R234.1 U5.J3 | length 57.4
  Top Layer w0.1: v1(45.2,146.685) CN6.9@47.293,146.685 ; v2(82.4,138.8) U5.J3@82.8,138.4
  Signal Layer 2 w0.1: v1(45.2,146.685) 43.688,148.197 43.688,152.273 44.515,153.1 54.291,153.1 59.055,148.336 77.47,148.336 82.4,143.406 v2(82.4,138.8)
  Bottom Layer w0.127: R234.1@44.392,146.685 v1(45.2,146.685)
PF7: CN6.7 R230.1 U5.J4 | length 55.6
  Top Layer w0.1: v1(45.2,147.955) CN6.7@47.293,147.955 ; v2(82.4,138) U5.J4@82.8,137.6
  Signal Layer 2 w0.1: v1(45.2,147.955) 44.069,149.086 44.069,152.019 44.75,152.7 54.183,152.7 58.928,147.955 77.343,147.955 82,143.298 82,138.4 v2(82.4,138)
  Bottom Layer w0.127: R230.1@44.392,147.955 v1(45.2,147.955)
PF8: CN6.11 R237.1 U5.K1 | length 43.5
  Top Layer w0.1: v1(45.2,145.415) CN6.11@47.293,145.415 ; v2(79.375,143.891) 79.952,143.314 80.45,143.314 80.519,143.383 81.153,143.383 82,142.536 U5.K1@82,140
  Signal Layer 2 w0.1: v1(45.2,145.415) 52.5,145.415 53.115,144.8 78.466,144.8 v2(79.375,143.891)
  Bottom Layer w0.127: R237.1@44.392,145.415 v1(45.2,145.415)
PF9: CN6.13 R241.1 U5.K2 | length 43.2
  Top Layer w0.1: v1(45.2,144.145) CN6.13@47.293,144.145 ; v2(79.375,143.256) 79.375,143.087 81.6,140.862 81.6,139.6 U5.K2@82,139.2
  Signal Layer 2 w0.1: v1(45.2,144.145) 53.2,144.145 53.745,143.6 54.7,143.6 55.499,144.399 78.232,144.399 v2(79.375,143.256)
  Bottom Layer w0.127: R241.1@44.392,144.145 v1(45.2,144.145)
PF10: CN5.7 JP15.1 R15.1 U5.M3 | length 66.4
  Top Layer w0.127: v2(80,138.8) U5.M3@80.4,138.4 ; v1(123.825,148.59) 124.079,148.336 130.175,148.336 130.937,149.098 JP15.1@135.89,149.098 135.948,149.156 R15.1@135.948,151.13
  Top Layer w0.2: v1(113.85,147.955) CN5.7@115.872,147.955
  Signal Layer 2 w0.1: v2(86.4,138.8) 86.8,138.8 87.6,139.6 87.6,141.448 90.805,144.653 95.25,144.653 96.393,145.796 110.744,145.796 112.903,147.955 v1(113.85,147.955) 120.142,147.955 120.777,148.59 v1(123.825,148.59)
  Signal Layer 4 w0.1: v2(80,138.8) 80.4,139.2 86,139.2 v2(86.4,138.8)
PF11: CN12.8 R332.1 U5.N8 | length 59.1
  Top Layer w0.1: 74.4,134.1 78.3,134.1 78.5,133.9 79.1,133.9 U5.N8@79.6,134.4
  Top Layer w0.127: CN12.8@62.373,108.585 v1(64.262,108.585) ; v2(68.6,129.433) 67.31,129.433 67.183,129.56 67.183,129.794 67.31,129.921 68.58,129.921 68.707,130.048 68.707,130.302 68.58,130.429 67.31,130.429 67.183,130.556 67.183,130.81 67.31,130.937 70.104,130.937 72.39,133.223 73.523,133.223 74.4,134.1
  Bottom Layer w0.127: R332.1@63.442,108.585 v1(64.262,108.585) 64.897,109.22 64.897,110.49 65.913,111.506 65.913,120.777 68.199,123.063 68.199,124.841 68.58,125.222 68.58,126.873 68.453,127 68.072,127 67.945,127.127 67.945,127.381 68.072,127.508 68.453,127.508 68.58,127.635 68.58,127.889 68.453,128.016 66.421,128.016 66.294,128.143 66.294,128.397 66.421,128.524 68.199,128.524 68.326,128.651 68.326,128.905 68.199,129.032 66.421,129.032 66.294,129.159 66.294,129.413 66.421,129.54 67.945,129.54 68.072,129.667 68.072,129.921 67.945,130.048 66.548,130.048 66.421,130.175 66.421,130.429 66.548,130.556 68.346,130.556 68.6,130.302 v2(68.6,129.433)
PF12: CN12.5 R72.2 R326.1 U5.R9 | length 60.5
  Top Layer w0.127: R72.2@54.294,109.855 v1(55.251,109.855) CN12.5@57.273,109.855 ; v1(64.389,125.349) 63.119,125.349 62.865,125.603 62.865,127 62.992,127.127 63.246,127.127 63.373,127 63.373,125.984 63.5,125.857 63.754,125.857 63.881,125.984 63.881,127 64.008,127.127 64.262,127.127 64.389,127 64.389,126.111 64.516,125.984 64.77,125.984 64.897,126.111 64.897,127 65.024,127.127 67.627,127.127 72.961,132.461 73.761,132.461 74.9,133.6 U5.R9@78,133.6
  Bottom Layer w0.127: R326.1@56.188,109.855 v1(55.251,109.855) 54.991,109.595 54.229,109.595 54.102,109.722 54.102,109.982 54.229,110.109 54.483,110.109 54.61,110.236 54.61,112.522 54.991,112.903 58.166,112.903 61.341,116.078 61.341,125.603 61.849,126.111 61.849,127.381 61.976,127.508 62.23,127.508 62.357,127.381 62.357,126.111 62.484,125.984 62.738,125.984 62.865,126.111 62.865,127.381 62.992,127.508 63.246,127.508 63.373,127.381 63.373,125.603 63.627,125.349 v1(64.389,125.349)
PF13: CN12.3 R325.1 U5.M8 | length 59.2
  Top Layer w0.1: 74.742,132.942 75.1,133.3 79,133.3 79.2,133.5 79.2,133.7 79.5,134 80,134 U5.M8@80.4,134.4
  Top Layer w0.127: v1(55.251,111.125) CN12.3@57.273,111.125 ; v2(65.405,125.476) 65.278,125.603 65.278,126.619 65.405,126.746 65.659,126.746 65.786,126.619 65.786,125.857 65.913,125.73 66.167,125.73 66.294,125.857 66.294,126.619 66.421,126.746 66.675,126.746 66.802,126.619 66.802,125.857 66.929,125.73 67.183,125.73 67.31,125.857 67.31,126.619 67.437,126.746 67.818,126.746 73.152,132.08 73.88,132.08 74.742,132.942
  Bottom Layer w0.127: v1(55.251,111.125) R325.1@56.188,111.125 56.188,111.814 56.388,112.014 57.785,112.014 57.912,111.887 57.912,111.252 58.039,111.125 58.293,111.125 58.42,111.252 58.42,112.141 59.817,113.538 61.468,113.538 61.595,113.411 61.595,113.03 61.722,112.903 61.976,112.903 62.103,113.03 62.103,113.919 61.976,114.046 60.96,114.046 60.833,114.173 60.833,114.427 60.96,114.554 61.976,114.554 62.103,114.681 62.103,121.412 64.897,124.206 64.897,125.73 64.643,125.984 64.008,125.984 63.881,126.111 63.881,126.365 64.008,126.492 64.77,126.492 64.897,126.619 64.897,126.873 64.77,127 64.008,127 63.881,127.127 63.881,127.381 64.008,127.508 65.024,127.508 65.405,127.127 v2(65.405,125.476)
PF14: CN12.4 R70.1 U5.P9 | length 58.9
  Top Layer w0.1: 74.446,133.646 74.7,133.9 78.2,133.9 78.5,133.6 U5.P9@78.8,133.6
  Top Layer w0.127: CN12.4@62.373,111.125 v1(64.262,111.125) R70.1@65.336,111.125 ; v2(67.422,127.523) 65.644,127.523 65.532,127.635 65.532,127.889 65.659,128.016 67.945,128.016 68.072,128.143 68.072,128.397 67.945,128.524 65.659,128.524 65.532,128.651 65.532,128.905 65.659,129.032 68.961,129.032 69.596,129.667 69.596,129.921 69.469,130.048 69.327,130.048 69.2,130.175 69.2,130.414 69.342,130.556 70.456,130.556 72.742,132.842 73.642,132.842 74.032,133.232 74.446,133.646
  Bottom Layer w0.127: v1(64.262,111.125) 64.389,111.125 65.151,111.887 65.151,113.284 64.008,114.427 64.008,114.935 63.881,115.062 63.373,115.062 63.246,115.189 63.246,115.443 63.373,115.57 63.881,115.57 64.008,115.697 64.008,115.951 63.881,116.078 63.373,116.078 63.246,116.205 63.246,116.459 63.373,116.586 63.881,116.586 64.008,116.713 64.008,116.967 63.881,117.094 63.373,117.094 63.246,117.221 63.246,117.475 63.373,117.602 63.881,117.602 64.008,117.729 64.008,117.983 63.881,118.11 63.373,118.11 63.246,118.237 63.246,118.491 63.373,118.618 63.881,118.618 64.008,118.745 64.008,118.999 63.881,119.126 63.373,119.126 63.246,119.253 63.246,119.507 63.373,119.634 63.881,119.634 64.008,119.761 64.008,120.015 63.881,120.142 63.373,120.142 63.246,120.269 63.246,120.523 63.373,120.65 63.881,120.65 64.008,120.777 64.008,121.539 66.929,124.46 66.929,124.714 66.802,124.841 66.421,124.841 66.294,124.968 66.294,125.222 66.421,125.349 67.31,125.349 67.437,125.476 67.437,125.73 67.31,125.857 66.421,125.857 66.294,125.984 66.294,126.238 66.421,126.365 67.31,126.365 67.437,126.492 67.437,126.746 67.31,126.873 66.421,126.873 66.294,127 66.294,127.254 66.421,127.381 67.422,127.381 v2(67.422,127.523)
PF15: CN12.18 R103.1 U5.N9 | length 59.7
  Top Layer w0.1: 75.221,132.821 75.5,133.1 79.1,133.1 U5.N9@79.6,133.6
  Top Layer w0.127: CN12.18@62.373,102.235 v1(64.262,102.235) R103.1@65.336,102.235 ; v2(70.485,128.46) 70.485,128.905 70.675,129.095 70.802,129.095 71.12,128.778 71.247,128.778 71.501,129.032 71.501,129.159 71.183,129.476 71.183,129.603 73.279,131.699 74.099,131.699 75.221,132.821
  Bottom Layer w0.127: v1(64.262,102.235) 65.532,103.505 65.532,105.537 67.341,107.346 67.533,107.346 68.375,106.504 68.531,106.504 68.77,106.743 68.77,106.871 67.875,107.766 67.875,107.88 68.135,108.14 68.262,108.14 68.389,108.013 68.516,108.013 68.77,108.267 68.77,108.394 68.643,108.521 68.643,108.648 72.136,112.141 72.136,112.268 72.009,112.395 71.374,112.395 71.247,112.522 71.247,112.776 71.374,112.903 72.009,112.903 72.136,113.03 72.136,113.284 72.009,113.411 71.374,113.411 71.247,113.538 71.247,113.792 71.374,113.919 72.009,113.919 72.136,114.046 72.136,124.714 72.009,124.841 71.501,124.841 71.374,124.968 71.374,125.222 71.501,125.349 72.009,125.349 72.136,125.476 72.136,125.73 72.009,125.857 71.12,125.857 70.993,125.984 70.993,126.238 71.12,126.365 72.009,126.365 72.136,126.492 72.136,126.746 72.009,126.873 69.85,126.873 69.723,127 69.723,127.254 69.85,127.381 70.993,127.381 71.12,127.508 71.12,127.762 70.993,127.889 69.85,127.889 69.723,128.016 69.723,128.27 69.913,128.46 v2(70.485,128.46)
PG0: CN12.6 R73.2 R76.2 U5.R10 | length 61.1
  Top Layer w0.127: CN12.6@62.373,109.855 v1(64.262,109.855) R73.2@65.336,109.855 R76.2@65.336,108.712 ; v2(67.8,126.093) 69.723,128.016 71.12,128.016 75.904,132.8 U5.R10@78,132.8
  Bottom Layer w0.127: v1(64.262,109.855) 64.262,109.347 64.135,109.22 62.611,109.22 62.484,109.347 62.484,109.601 62.611,109.728 63.373,109.728 63.5,109.855 63.5,110.109 63.373,110.236 62.484,110.236 62.357,110.363 62.357,110.617 62.484,110.744 63.881,110.744 64.135,110.49 64.389,110.49 65.532,111.633 65.532,113.919 65.405,114.046 64.897,114.046 64.77,114.173 64.77,114.427 64.897,114.554 65.405,114.554 65.532,114.681 65.532,114.935 65.405,115.062 64.516,115.062 64.389,115.189 64.389,115.443 64.516,115.57 65.405,115.57 65.532,115.697 65.532,115.951 65.405,116.078 64.516,116.078 64.389,116.205 64.389,116.459 64.516,116.586 65.405,116.586 65.532,116.713 65.532,116.967 65.405,117.094 64.516,117.094 64.389,117.221 64.389,117.475 64.516,117.602 65.405,117.602 65.532,117.729 65.532,117.983 65.405,118.11 64.516,118.11 64.389,118.237 64.389,118.491 64.516,118.618 65.405,118.618 65.532,118.745 65.532,118.999 65.405,119.126 64.516,119.126 64.389,119.253 64.389,119.507 64.516,119.634 65.405,119.634 65.532,119.761 65.532,120.015 65.405,120.142 64.516,120.142 64.389,120.269 64.389,120.523 64.516,120.65 65.405,120.65 65.532,120.777 65.532,121.031 65.405,121.158 64.77,121.158 64.643,121.285 64.643,121.539 64.77,121.666 66.294,121.666 66.421,121.793 66.421,121.92 65.786,122.555 65.786,122.682 66.04,122.936 66.167,122.936 66.802,122.301 66.929,122.301 67.183,122.555 67.183,122.682 66.548,123.317 66.548,123.444 66.802,123.698 66.929,123.698 67.437,123.19 67.564,123.19 67.8,123.426 67.8,124.95 68.199,125.349 68.199,125.984 68.09,126.093 v2(67.8,126.093)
